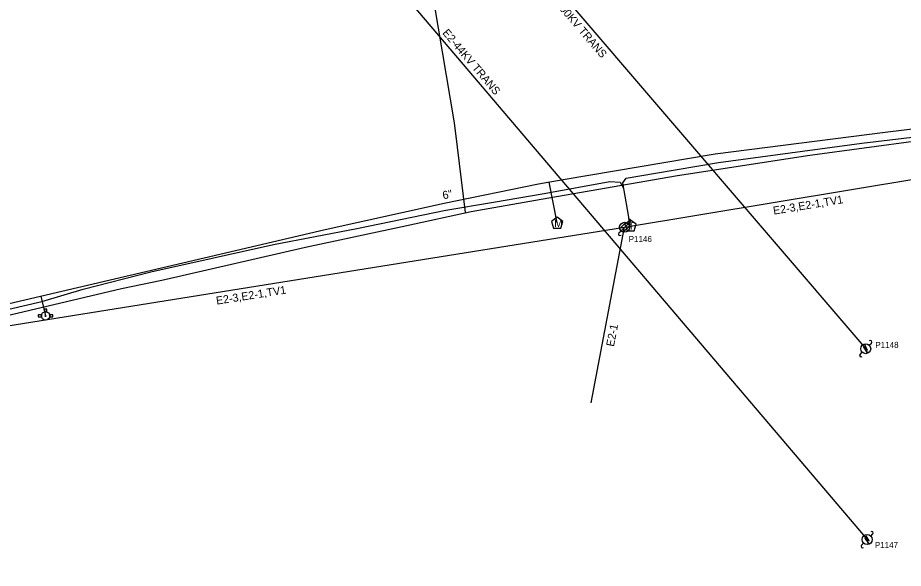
# Model space of a CAD drawing. Extents: x 1614474 to 1865144, y 1098877 to 1212550.
# Drawn here: x 1807840.3 to 1808283, y 1189692.3 to 1189967.8 of the extents above; entities that cross this region are included whole.
import ezdxf

# ---------------------------------------------------------------- set-up
doc = ezdxf.new("R2010")
doc.units = 0
for name, color, linetype in [('RD_EX_SU_Elec', 7, 'Continuous'), ('RD_EX_SU_Gas', 7, 'Continuous'), ('RD_EX_SU_H2O', 7, 'Continuous'), ('RD_EX_SU_Ovhd', 7, 'Continuous'), ('RD_EX_SU_Pole', 7, 'Continuous'), ('RD_EX_SU_Telecom', 7, 'Continuous'), ('RD_EX_SU_TX_H2O', 7, 'Continuous'), ('RD_EX_SU_TX_Pole', 7, 'Continuous')]:
    doc.layers.add(name, color=color, linetype=linetype)

# ---------------------------------------------------------------- blocks, each defined once
blk = doc.blocks.new('SUE_TPP')
at = {"layer": 'RD_EX_SU_Telecom'}
blk.add_lwpolyline([(0, 3), (-2.85, 0.93), (-1.76, -2.43), (1.76, -2.43), (2.85, 0.93)], close=True, dxfattribs=at)
blk.add_text('T', height=3.75, dxfattribs=at).set_placement((-1.25, -1.88))
blk = doc.blocks.new('SUE_WFH')
at = {"layer": 'RD_EX_SU_H2O'}
for p, q in [((-2.01, 0.6), (-3.65, 0.6)), ((-3.65, 0.6), (-3.65, -0.45)), ((-0.48, 3.38), (-0.48, 2.04)), ((0.57, 3.38), (-0.48, 3.38)), ((0.57, 2.02), (0.57, 3.38)), ((3.7, 0.6), (2.01, 0.6)), ((3.7, -0.45), (3.7, 0.6)), ((-3.65, -0.45), (-2.05, -0.45)), ((2.05, -0.45), (3.7, -0.45))]:
    blk.add_line(p, q, dxfattribs=at)
for radius in [2.1, 0.263]:
    blk.add_circle((0, 0), radius, dxfattribs=at)
for start, end in [(163.3387, 192.315), (74.2455, 103.2128), (347.685, 16.6613)]:
    blk.add_arc((0, 0), 2.1, start, end, dxfattribs=at)
blk = doc.blocks.new('SUE_WM')
at = {"layer": 'RD_EX_SU_H2O'}
blk.add_lwpolyline([(0, 3.05), (-2.9, 0.94), (-1.79, -2.47), (1.79, -2.47), (2.9, 0.94)], close=True, dxfattribs=at)
blk.add_text('M', height=3.75, dxfattribs=at).set_placement((-1.43, -1.88))
blk = doc.blocks.new('SUE_PLT')
at = {"layer": 'RD_EX_SU_Elec'}
for p, q in [((1.77, 1.77), (2.83, 2.83)), ((-2.83, -2.83), (-1.77, -1.77))]:
    blk.add_line(p, q, dxfattribs=at)
blk.add_lwpolyline([(-0.49, 1.95), (0.34, -0.06), (-1.12, 0.74), (0.75, -1.95), (0.75, -1.95), (-0.45, 0.15), (0.94, -0.65)], close=True, dxfattribs=at)
blk.add_circle((0, 0), 2.5, dxfattribs=at)
for centre, start, end in [((2.3, 3.36), 315, 135), ((-2.3, -3.36), 135, 315)]:
    blk.add_arc(centre, 0.75, start, end, dxfattribs=at)

msp = doc.modelspace()

# ---------------------------------------------------------------- linework, layer by layer
at = {"layer": 'RD_EX_SU_Gas'}
for points in [[(1808026.79, 1190089.68), (1808029.01, 1190078.01), (1808033.59, 1190056.77), (1808036.58, 1190044.53), (1808058.46, 1189915.21), (1808059.92, 1189902.95), (1808064.02, 1189870.22)], [(1807892.2, 1189832.29), (1807912.28, 1189836.42), (1807984.19, 1189853.03), (1808034.88, 1189863.81), (1808066.94, 1189870.87), (1808102.04, 1189876.93), (1808170.12, 1189888.84), (1808236.25, 1189898.91), (1808290.63, 1189906.28)], [(1807202.55, 1189593.86), (1807244.4, 1189612.02), (1807273.79, 1189625.62), (1807328.26, 1189647.9), (1807387.74, 1189671.88), (1807435.65, 1189690.41), (1807484.25, 1189709.27), (1807520.29, 1189722.4), (1807589.39, 1189747.97), (1807628.2, 1189761.41), (1807638.08, 1189764.18), (1807691.6, 1189781.97), (1807738, 1189797.04), (1807818.59, 1189814.89), (1807892.2, 1189832.29)]]:
    msp.add_lwpolyline(points, dxfattribs=at)
at = {"layer": 'RD_EX_SU_H2O'}
for p, q in [((1808100.62, 1189884.58), (1808113.01, 1189886.79)), ((1808105.88, 1189885.52), (1808109.85, 1189865.13)), ((1807851.87, 1189828.47), (1807854.19, 1189818.53))]:
    msp.add_line(p, q, dxfattribs=at)
for points in [[(1808113.01, 1189886.79), (1808188.98, 1189899.61), (1808273.96, 1189910.47), (1808404.4, 1189926.58), (1808543.88, 1189936.56)], [(1807642.08, 1189770.78), (1807764.43, 1189806.14), (1807817.32, 1189820.38), (1807994.06, 1189861.76), (1808053.5, 1189874.9), (1808100.62, 1189884.58)]]:
    msp.add_lwpolyline(points, dxfattribs=at)
at = {"layer": 'RD_EX_SU_Ovhd'}
for p, q in [((1807906.34, 1190220.38), (1808264.24, 1189802.13)), ((1807844.31, 1190202.03), (1808264.96, 1189706.62)), ((1808143.68, 1189862.89), (1808344.36, 1189896.23)), ((1807826.32, 1189812.08), (1808143.68, 1189862.89)), ((1808126.9, 1189775.04), (1808143.68, 1189862.89))]:
    msp.add_line(p, q, dxfattribs=at)
at = {"layer": 'RD_EX_SU_Pole'}
for p, q in [((1808141.26, 1189862.24), (1808144.33, 1189865.31)), ((1808141.91, 1189861.12), (1808145.45, 1189864.66)), ((1808143.03, 1189860.48), (1808146.09, 1189863.54)), ((1808145.45, 1189864.66), (1808146.51, 1189865.72)), ((1808140.85, 1189860.06), (1808141.91, 1189861.12)), ((1808266.01, 1189803.9), (1808267.07, 1189804.96)), ((1808261.41, 1189799.3), (1808262.47, 1189800.37))]:
    msp.add_line(p, q, dxfattribs=at)
msp.add_lwpolyline([(1808263.75, 1189804.08), (1808264.58, 1189802.07), (1808263.12, 1189802.87), (1808265, 1189800.19), (1808265, 1189800.19), (1808263.79, 1189802.28), (1808265.18, 1189801.48)], close=True, dxfattribs=at)
for centre in [(1808143.68, 1189862.89), (1808264.24, 1189802.13)]:
    msp.add_circle(centre, 2.5, dxfattribs=at)
for centre, start, end in [((1808145.98, 1189866.25), 315, 135), ((1808141.38, 1189859.53), 135, 315), ((1808266.54, 1189805.49), 315, 135), ((1808261.94, 1189798.77), 135, 315)]:
    msp.add_arc(centre, 0.75, start, end, dxfattribs=at)
at = {"layer": 'RD_EX_SU_Telecom'}
for points in [[(1808146.52, 1189864.03), (1808145.06, 1189871.87), (1808142.75, 1189885.18), (1808144.4, 1189887.44), (1808159.18, 1189889.94), (1808190.57, 1189895.24), (1808262.24, 1189904.93), (1808328.14, 1189912.78), (1808349.25, 1189915.24), (1808388.41, 1189920.5), (1808438.37, 1189925.56), (1808498.46, 1189928.86), (1808545.57, 1189930.88), (1808565.48, 1189932.68), (1808605.01, 1189934.53), (1808636.97, 1189935.48), (1808665.04, 1189936.36), (1808702.98, 1189938.65), (1808748.15, 1189940.04), (1808764.45, 1189940.02), (1808766.32, 1189933.12)], [(1807804.88, 1189814.7), (1807852.38, 1189825.77), (1807872.94, 1189831.87), (1807906.82, 1189840.64), (1807968.17, 1189854.28), (1808009.86, 1189862.32), (1808054.35, 1189871.48), (1808078.14, 1189875.46), (1808103.5, 1189879.86), (1808136.32, 1189885.79), (1808141.4, 1189885.5), (1808143.22, 1189882.49)]]:
    msp.add_lwpolyline(points, dxfattribs=at)

# ---------------------------------------------------------------- block references
at = {"layer": 'RD_EX_SU_Elec'}
msp.add_blockref('SUE_PLT', (1808264.96, 1189706.62), dxfattribs=at)
at = {"layer": 'RD_EX_SU_H2O'}
for name, p in [('SUE_WM', (1808109.98, 1189864.86)), ('SUE_WFH', (1807854.19, 1189818.53))]:
    msp.add_blockref(name, p, dxfattribs=at)
at = {"layer": 'RD_EX_SU_Telecom'}
msp.add_blockref('SUE_TPP', (1808146.69, 1189863.54), dxfattribs=at)

# ---------------------------------------------------------------- texts
at = {"layer": 'RD_EX_SU_Ovhd'}
for s, rotation, p in [('E2-100KV TRANS', 310.5543, (1808103.55, 1189980.69)), ('E2-44KV TRANS', 310.2791, (1808052.36, 1189960.03)), ('E2-3,E2-1,TV1', 9.4321, (1808218.28, 1189869.2)), ('E2-3,E2-1,TV1', 9.097, (1807939.77, 1189824.16)), ('E2-1', 79.1869, (1808138.34, 1189802.96))]:
    msp.add_text(s, height=4, rotation=rotation, dxfattribs=at).set_placement(p)
at = {"layer": 'RD_EX_SU_TX_H2O'}
msp.add_text('6"', height=4, rotation=11.6063, dxfattribs=at).set_placement((1808053.08, 1189876.86))
at = {"layer": 'RD_EX_SU_TX_Pole'}
for s, p in [('P1146', (1808145.73, 1189855.54)), ('P1148', (1808269.08, 1189802.57)), ('P1147', (1808268.82, 1189702.42))]:
    msp.add_text(s, height=3, dxfattribs=at).set_placement(p)

doc.saveas('drawing.dxf')
